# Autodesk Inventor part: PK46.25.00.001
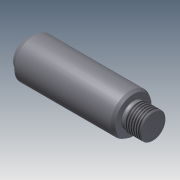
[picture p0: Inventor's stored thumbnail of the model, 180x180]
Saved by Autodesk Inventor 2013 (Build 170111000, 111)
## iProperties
Created: 2005-05
Part Number: PK46.25.00.001
Material: Steel, Mild
Document SubType Name: Modeling
Designer: PVitaliy
Manufacturer: Standard
Standards Organization: Custom
Density: 7.86 g/cm^3
Author: PVitaliy
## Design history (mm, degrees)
sketch "Эскиз2"
  geometry: L1 (0, 0)-(95.139, 0); L2 (0, 0)-(0, 27.494); L3 (0, 27.494)-(13, 35); L4 (13, 35)-(15, 35); L5 (15, 35)-(15, 40); L6 (15, 40)-(209, 40); L7 (209, 40)-(215, 36.536); L8 (215, 36.536)-(215, 24.5); L9 (215, 24.5)-(221, 24.5); L10 (221, 24.5)-(222.5, 26); L11 (222.5, 26)-(255, 26); L12 (255, 26)-(255, 0); L13 (255, 0)-(0, 0)
  constraints: 26 end point, 6 horizontal, 4 vertical, 1 other
  dimensions: "d0" = 70 diameter of L4 L1; "d1" = 30 deg angle of L3 L4; "d2" = 15 distance between parallel lines of L5 L2; "d3" = 2 distance of L3.end L4.end; "d4" = 80 diameter of L6 L1; "d5" = 200 distance between parallel lines of L8 L5; "d6" = 30 deg angle of L6 L7; "d7" = 6 horizontal distance of L6.end L7.end; "d8" = 255 distance between parallel lines of L12 L2; "d9" = 52 diameter of L11 L1; "d10" = 6 distance of L8.end L9.end; "d11" = 49 diameter of L9 L1; "d12" = 45 deg angle of L10 L9
revolve "Вращение1" sketch "Эскиз2" stored, may be unused: angle "d13" = 90 deg
feature "Резьба1" dims "d14" = 10, "d15" = 0
chamfer "Фаска1" distance "d16" = 1.6; stored, may be unused: second distance "d17" = 2, angle "d18" = 45 deg
fillet "Сопряжение1" dims "d19" = 1, "d20" = 0.5
body "Solid1"
